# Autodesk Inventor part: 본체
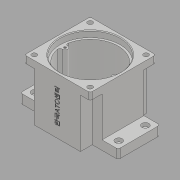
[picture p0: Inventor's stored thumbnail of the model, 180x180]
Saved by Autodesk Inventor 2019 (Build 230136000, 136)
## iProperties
Created: 2020-01
Part Number: 본체
Material: 알루미늄 6061
Document SubType Name: Modeling
Designer: 323-17
Density: 2.7 g/cm^3
Appearance: 기본값
Mass: 876.342 g
Surface Area: 793.825 cm^2
Volume: 324.571 cm^3
Author: 323-17
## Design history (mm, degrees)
sketch "스케치1"
  geometry: L1 (47, 47)-(-47, 47); L2 (-47, 47)-(-47, -47); L3 (-47, -47)-(47, -47); L4 (47, -47)-(47, 47); L5 (47, 47)-(-47, -47); L6 (-47, 47)-(47, -47); 1 further point
  constraints: 12 end point, 2 midpoint, 2 parallel, 1 horizontal, 1 perpendicular
  dimensions: "d0" = 94 distance of L3.end L2.end; "d1" = 94 distance of L2.end L1.end
extrude "돌출1" new body sketch "스케치1" distance "d2" = 80; taper "d3" = 0 deg
sketch "스케치2"
  geometry: L1 (70, 30)-(-70, 30); L2 (-70, 30)-(-70, -30); L3 (-70, -30)-(70, -30); L4 (70, -30)-(70, 30); L5 (70, 30)-(-70, -30); L6 (-70, 30)-(70, -30); 1 further point
  constraints: 12 end point, 2 midpoint, 2 parallel, 1 horizontal, 1 perpendicular
  dimensions: "d4" = 140 distance of L3.end L2.end; "d5" = 60 distance of L2.end L1.end
extrude "돌출2" join sketch "스케치2" distance "d6" = 13; taper "d7" = 0 deg
sketch "스케치3"
  geometry: L1 (-33, -47)-(33, -47); L2 (33, -47)-(33, 47); L3 (33, 47)-(-33, 47); L4 (-33, 47)-(-33, -47); L5 (-33, -47)-(33, 47); L6 (33, -47)-(-33, 47); L7 (-47, 30)-(-70, 30) reference; L8 (70, -30)-(-70, -30); L9 (-70, -30)-(-70, 30); L10 (-70, 30)-(70, 30); L11 (70, 30)-(70, -30); L12 (70, -30)-(-70, 30); L13 (-70, -30)-(70, 30); L14 (-33, 30)-(-33, 47); L15 (-47, 47)-(47, 47) reference; L16 (-47, 47)-(-47, 30); L17 (-47, 30)-(-33, 30); L18 (-33, 47)-(-47, 47); 1 further point
  constraints: 32 end point, 4 midpoint, 4 parallel, 3 perpendicular, 2 collinear, 2 horizontal, 2 point on line
  dimensions: "d8" = 66 distance of L3.end L2.end; "d9" = 94 distance of L2.end L1.end
extrude "돌출3" cut sketch "스케치3" distance "d10" = 70; taper "d11" = 0 deg
sketch "스케치4"
  geometry: C1 r 27.5 at (0, -11); 1 further point
  constraints: 1 centre point, 1 vertical alignment
  dimensions: "d12" = 55 diameter of C1; "d13" = 11 distance of point (0, 0) C1.centre
extrude "돌출4" join sketch "스케치4" distance "d14" = 7; taper "d15" = 0 deg
sketch "스케치5"
  geometry: C1 r 27.5 at (0, 0) reference; C2 r 16 at (0, 0); 1 further point
  constraints: 1 centre point, 1 coincident
  dimensions: "d16" = 32 diameter of C2
extrude "돌출5" cut sketch "스케치5" distance "d17" = 8.3; taper "d18" = 0 deg
sketch "스케치6"
  geometry: C1 r 43 at (0, 0); 1 further point
  constraints: 1 centre point, 1 coincident
  dimensions: "d19" = 86 diameter of C1
extrude "돌출6" cut sketch "스케치6" distance "d20" = 9; taper "d21" = 0 deg
sketch "스케치7"
  geometry: C1 r 40 at (0, 0); 1 further point
  constraints: 1 centre point, 1 coincident
  dimensions: "d22" = 80 diameter of C1
extrude "돌출7" cut sketch "스케치7" distance "d23" = 62; taper "d24" = 0 deg
sketch "스케치8"
  geometry: C1 r 21 at (0, 11); C2 r 15 at (0, -20); 1 further point
  constraints: 2 centre point, 2 vertical alignment
  dimensions: "d25" = 42 diameter of C1; "d26" = 11 distance of point (0, 0) C1.centre; "d27" = 30 diameter of C2; "d28" = 20 distance of point (0, 0) C2.centre
extrude "돌출8" join sketch "스케치8" distance "d29" = 7; taper "d30" = 0 deg
sketch "스케치9"
  geometry: C1 r 17.5 at (0, 11); A1 r 21 centre (0, 11) between (8.978, -7.984) and (-8.978, -7.984) reference; 1 further point
  constraints: 1 centre point, 1 coincident
  dimensions: "d31" = 35 diameter of C1
extrude "돌출9" cut sketch "스케치9" distance "d32" = 10; taper "d33" = 0 deg
sketch "스케치10"
  geometry: C1 r 17.5 at (0, 0) reference; C2 r 12.5 at (0, 0); 1 further point
  constraints: 1 centre point, 1 coincident
  dimensions: "d34" = 25 diameter of C2
extrude "돌출10" cut sketch "스케치10" extent not by distance; stored distance "d35" = 10; taper "d36" = 0 deg
sketch "스케치11"
  geometry: C1 r 11 at (0, -20); A1 r 15 centre (0, -20) between (-8.978, -7.984) and (8.978, -7.984) reference; 1 further point
  constraints: 1 centre point, 1 coincident
  dimensions: "d37" = 22 diameter of C1
extrude "돌출11" cut sketch "스케치11" distance "d38" = 7; taper "d39" = 0 deg
sketch "스케치12"
  geometry: C1 r 11 at (0, 0) reference; C2 r 9.5 at (0, 0); 1 further point
  constraints: 1 centre point, 1 coincident
  dimensions: "d40" = 19 diameter of C2
extrude "돌출12" cut sketch "스케치12" distance "d41" = 3; taper "d42" = 0 deg
sketch "스케치13" dims "d43" = 72
  geometry: L1 (-36, 4)-(-39.799, 4); L2 (-36, -4)-(-39.799, -4); A1 r 40 centre (0, 0) between (-39.799, 4) and (-39.799, -4) reference; A2 r 4 centre (-36, 0) between (-36, -4) and (-36, 4); A3 r 40 centre (0, 0) between (-39.799, 4) and (-39.799, -4); 3 further points
  constraints: 6 point on circle, 4 end point, 2 centre point, 2 coincident, 2 horizontal, 2 horizontal alignment, 2 tangent, 1 midpoint, 2 other
  dimensions: "d44" = 8 diameter of A2
extrude "돌출13" join sketch "스케치13" stored distance "d45" = 3; taper "d46" = 0 deg
sketch "스케치14"
  geometry: A1 r 4 centre (-36, 0) between (-36, -4) and (-36, 4) reference; 2 further points
  constraints: 1 coincident
hole "구멍1" sketch "스케치14" at (-36, 0) diameter "d47" = 3.242; stored, may be unused: countersink angle "d51" = 90 deg, drill point angle "d53" = 118 deg; dims "d48" = 7, "d49" = 10, "d50" = 4, "d52" = 9
sketch "스케치15"
  geometry: L1 (-40, -40)-(40, -40); L2 (40, -40)-(40, 40); L3 (40, 40)-(-40, 40); L4 (-40, 40)-(-40, -40); L5 (-40, -40)-(40, 40); L6 (40, -40)-(-40, 40); 1 further point
  constraints: 12 end point, 2 midpoint, 2 parallel, 1 horizontal, 1 perpendicular
  dimensions: "d54" = 80 distance of L3.end L2.end; "d55" = 80 distance of L2.end L1.end
hole "구멍2" sketch "스케치15" at (40, 40) diameter "d56" = 7; stored, may be unused: countersink angle "d60" = 90 deg, drill point angle "d62" = 118 deg; dims "d57" = 7, "d58" = 10, "d59" = 4, "d61" = 9
sketch "스케치16"
  geometry: L1 (60, -19)-(-60, -19); L2 (-60, -19)-(-60, 19); L3 (-60, 19)-(60, 19); L4 (60, 19)-(60, -19); L5 (60, -19)-(-60, 19); L6 (-60, -19)-(60, 19); 1 further point
  constraints: 12 end point, 2 midpoint, 2 parallel, 1 horizontal, 1 perpendicular
  dimensions: "d63" = 120 distance of L2.end L3.end; "d64" = 38 distance of L1.end L2.end
hole "구멍3" sketch "스케치16" at (-60, 19) diameter "d65" = 4.5; stored, may be unused: countersink angle "d69" = 90 deg, drill point angle "d71" = 118 deg; dims "d66" = 7, "d67" = 10, "d68" = 5, "d70" = 9
chamfer "모따기1" distance "d72" = 0.8; stored, may be unused: second distance "d73" = 2, angle "d74" = 30 deg
fillet "모깎기2" dims "d76" = 3
chamfer "모따기2" distance "d77" = 1; stored, may be unused: second distance "d78" = 2, angle "d79" = 30 deg
chamfer "모따기3" distance "d80" = 1; stored, may be unused: second distance "d81" = 2, angle "d82" = 30 deg
sketch "스케치17"
  geometry: L1 (-11, 80)-(77, 80) reference; L2 (0, 0)-(66, 0) reference; 3 further points
  constraints: 1 midpoint, 1 vertical alignment, 1 other
  dimensions: "d83" = 40 distance from line of L1 point (33, 40)
feature "엠보싱1" sketch "스케치17" dims "d0" = 94, "d1" = 94, "d8" = 66, "d9" = 94, "d84" = 0.5, "d85" = 0
node "솔리드1"
mirror "미러1"
mirror "미러2"
mirror "미러3"
mirror "미러4"
mirror "미러5"
mirror "미러6"
mirror "미러7"
node "투영된 루프1"
node "투영된 루프2"
node "투영된 루프3"
